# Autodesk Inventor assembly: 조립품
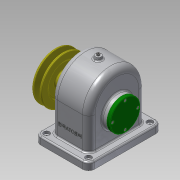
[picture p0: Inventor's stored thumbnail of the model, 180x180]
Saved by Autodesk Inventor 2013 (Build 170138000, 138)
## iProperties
Created: 2016-10
Part Number: 조립품
Document SubType Name: Assembly
Designer: Administrator
Author: Administrator
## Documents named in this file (15)
- C:\Users\Administrator\Desktop\461007V1002\조립품.iam
- C:\Users\Administrator\Desktop\461007V1002\본체.ipt
- C:\Users\Administrator\Desktop\461007V1002\461007V1002\V-벨트풀리.ipt
- C:\Users\Administrator\Desktop\461007V1002\461007V1002\뒤커버.ipt
- C:\Users\Administrator\Desktop\461007V1002\461007V1002\멈춤나사 - M4x10.ipt
- C:\Users\Administrator\Desktop\461007V1002\461007V1002\베어링 6203.ipt
- C:\Users\Administrator\Desktop\461007V1002\461007V1002\볼트 M3 x 8.ipt
- C:\Users\Administrator\Desktop\461007V1002\461007V1002\볼트 M3 x 10.ipt
- C:\Users\Administrator\Desktop\461007V1002\461007V1002\부시.ipt
- C:\Users\Administrator\Desktop\461007V1002\461007V1002\스퍼기어.ipt
- C:\Users\Administrator\Desktop\461007V1002\461007V1002\앞커버.ipt
- C:\Users\Administrator\Desktop\461007V1002\461007V1002\오일씰 28 40 8.ipt
- C:\Users\Administrator\Desktop\461007V1002\461007V1002\축.ipt
- C:\Users\Administrator\Desktop\461007V1002\461007V1002\키 - 5 x 5 x 18.ipt
- C:\Users\Administrator\Desktop\461007V1002\461007V1002\키 - 6 x 6 x 22.ipt
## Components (10 placed, 3 different names)
1. V-벨트풀리:1 — 각도:1
2. ISO 4762 M3 x 8:1
3. ISO 4762 M3 x 10:1
4. ISO 4762 M3 x 8:2
5. ISO 4762 M3 x 8:3
6. ISO 4762 M3 x 8:4
7. ISO 4762 M3 x 8:5
8. ISO 4762 M3 x 8:6
9. ISO 4762 M3 x 8:7
10. ISO 4762 M3 x 8:8
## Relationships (1: Angle 1)
- 각도:1 [Angle]: V-벨트풀리:1
